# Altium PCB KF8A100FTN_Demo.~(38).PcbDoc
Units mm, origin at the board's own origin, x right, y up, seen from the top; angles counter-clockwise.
Board outline 63.75 x 27.43 mm, 2 copper layers (Top Layer, Bottom Layer); 25 components, 35 nets, 113 pads, 5 vias.
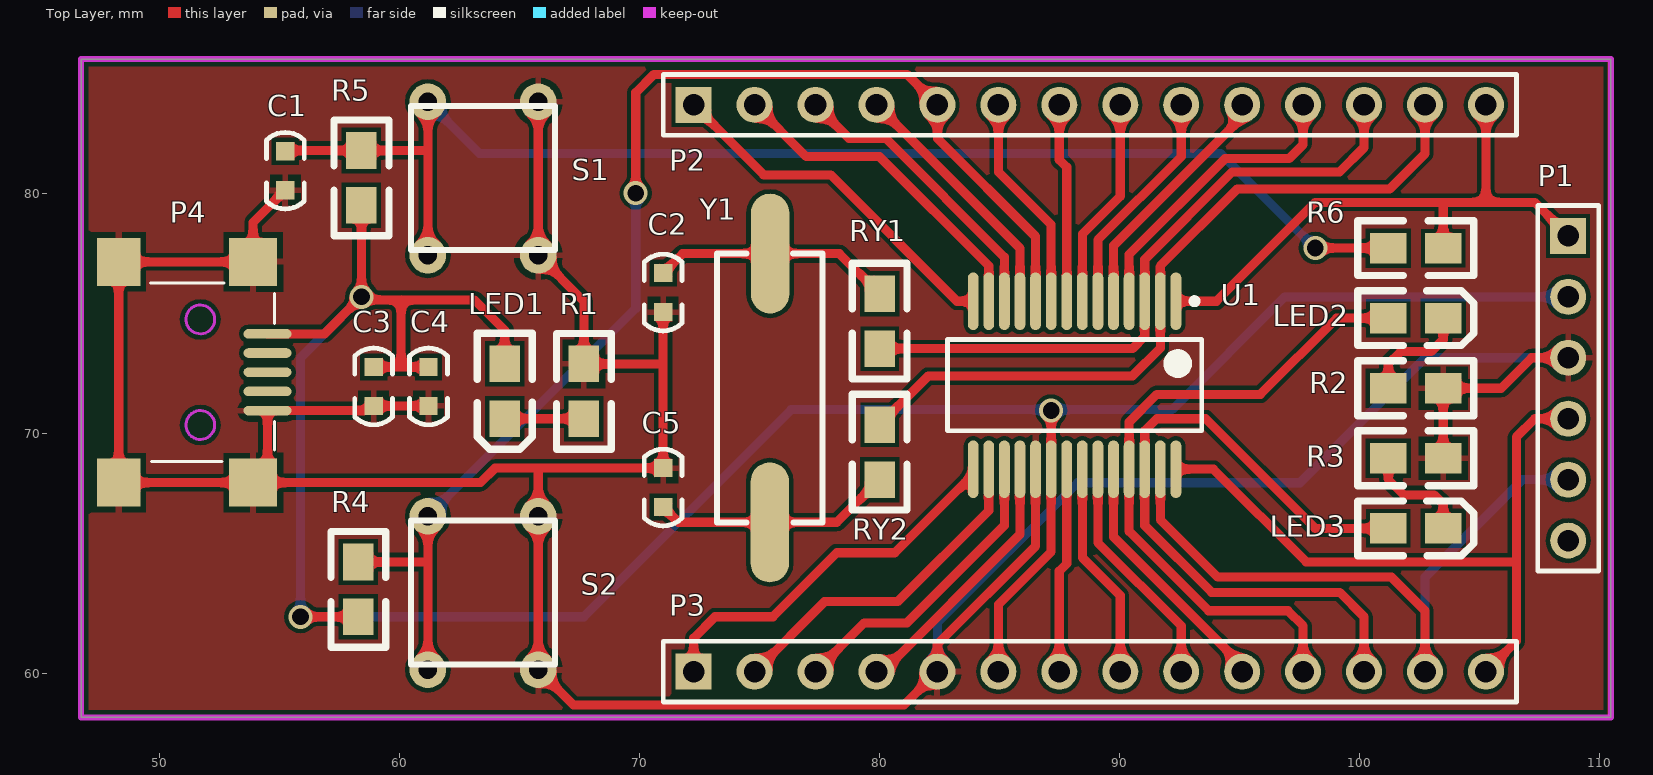
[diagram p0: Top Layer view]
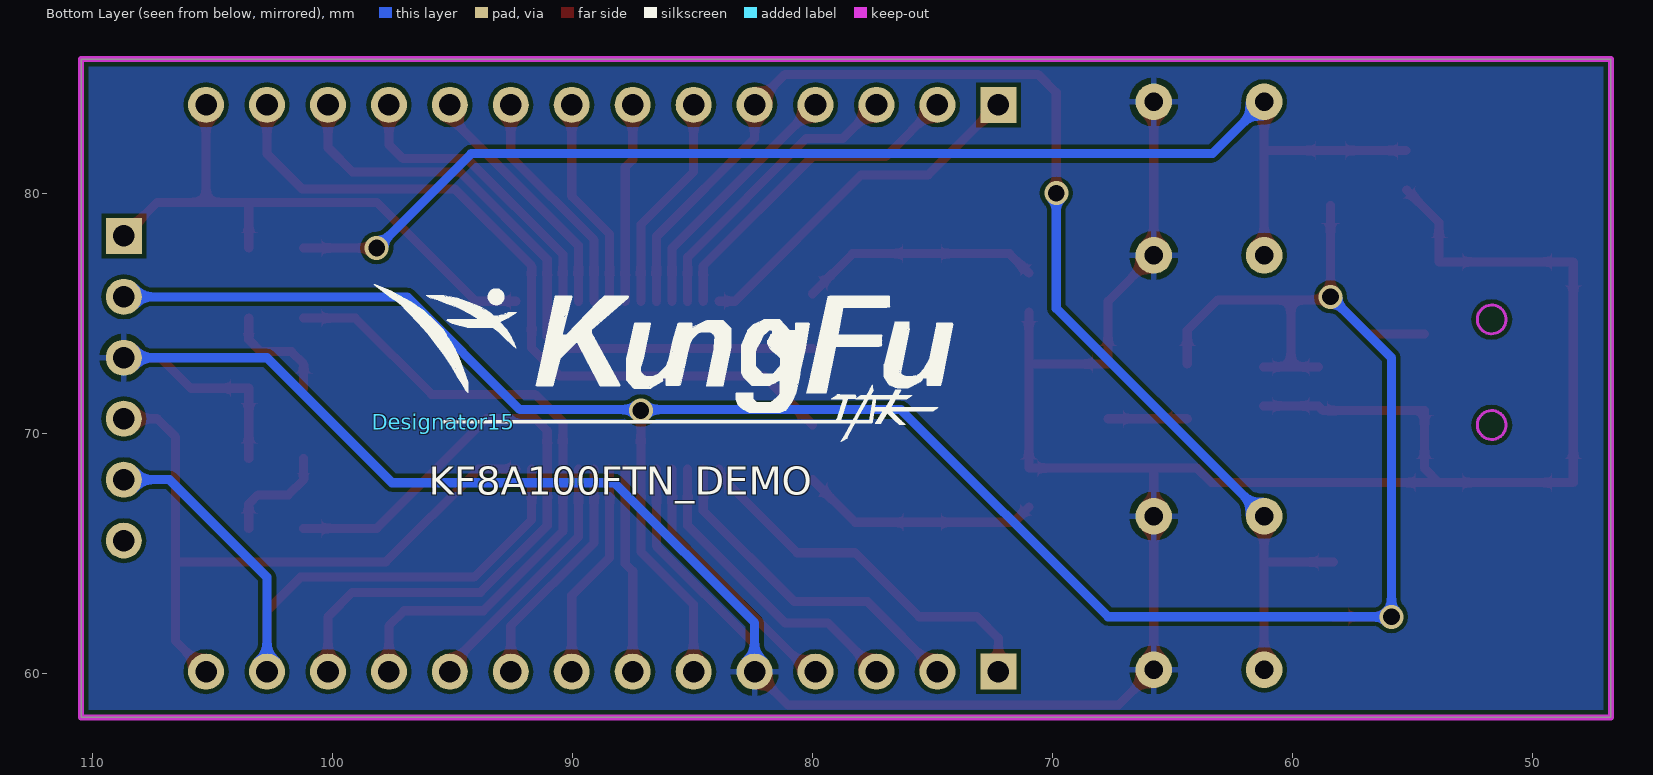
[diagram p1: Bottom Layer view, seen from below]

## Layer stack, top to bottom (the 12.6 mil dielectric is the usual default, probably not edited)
Top Solder: solder mask 0.0102, Solder Resist, Dk 3.5
Top Layer: signal copper 0.0356
Dielectric 1: dielectric 0.32, FR-4, Dk 4.8
Bottom Layer: signal copper 0.0356
Bottom Solder: solder mask 0.0102, Solder Resist, Dk 3.5

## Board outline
46.736,58.166 110.49,58.166 110.49,85.598 46.736,85.598

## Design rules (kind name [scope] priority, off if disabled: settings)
Clearance [All] p1: gap=0.178
PolygonConnect [All] p1: connectstyle=Relief reliefconductorwidth=0.254 reliefentries=4 polygonreliefangle="90 Angle" airgapwidth=0.254
RoutingVias [All] p1: holewidth=0.3 width=0.5 viastyle="Through Hole" minholewidth=0.3 minwidth=0.5 maxholewidth=0.7 maxwidth=1
SolderMaskExpansion [All] p1: expansion=0.102
UnpouredPolygon [All] p1: allowunpoured=FALSE
Width [All] p1: maxlimit=0.762 minlimit=0.254 preferedwidth=0.381
29 further rules are at their usual default settings.

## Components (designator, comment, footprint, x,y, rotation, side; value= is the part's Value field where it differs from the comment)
C1 "Comment" 0603C 55.245,80.137 r90 top
C2 "Comment" 0603C 70.993,75.057 r90 top
C3 "Comment" 0603C 58.928,72.771 r270 top
C4 "Comment" 0603C 61.214,72.771 r270 top
C5 "Comment" 0603C 70.993,66.929 r90 top
Designator15 "Comment" LOGO 95.377,70.485 r180 bottom
LED1 "Comment" D0805 64.389,72.898 r270 top
LED2 "Comment" D0805 101.216,74.803 r0 top
LED3 "Comment" D0805 101.216,66.04 r0 top
P1 "Comment" HDR1X6 108.712,78.232 r270 top
P2 "Comment" HDR1X14 72.263,83.693 r0 top
P3 "Comment" HDR1X14 72.263,60.071 r0 top
P4 "Comment" USB_MINI_B 51.562,73.406 r0 top
R1 "Comment" 0805 67.691,70.612 r90 top
R2 "Comment" 0805 101.219,71.882 r0 top
R3 "Comment" 0805 101.219,68.961 r0 top
R4 "Comment" 0805 58.293,62.357 r90 top
R5 "Comment" 0805 58.42,81.788 r270 top
R6 "Comment" 0805 101.219,77.724 r0 top
RY1 "Comment" 0805 80.01,75.819 r270 top
RY2 "Comment" 0805 80.01,70.358 r270 top
S1 "Comment" KEY6*6 65.786,83.82 r270 top
S2 "Comment" KEY6*6 65.786,66.548 r270 top
U1 "Comment" SSOP-SS28_M 88.138,72.009 r270 top
Y1 "Comment" CRYSTAL 75.438,66.294 r90 top

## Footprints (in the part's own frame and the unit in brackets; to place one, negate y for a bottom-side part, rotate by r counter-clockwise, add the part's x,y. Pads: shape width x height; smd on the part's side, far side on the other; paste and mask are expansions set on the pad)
0603C [mil]
  rect 30x30 smd: 1(0,0) 2(64,0)
  silkscreen extent -31,-31 95,31
0805 [mil]
  rect 60x50 smd: 1(-0.11,0) 2(89.89,0)
  silkscreen extent -50,-45 140,45
CRYSTAL [mm]
  oval 5x1.6 smd: 1(0,0) 2(11.2,-0.01)
  silkscreen extent 0,-2.2 11.2,2.2
D0805 [mil]
  rect 60x50 smd: 1(0,0) 2(90,0)
  silkscreen extent -50,-45 140,45
HDR1X6 [mm] "Connector; Header; 6 Position"
  rect 1.5x1.5 hole 0.9: 1(0,0)
  round 1.5 hole 0.9: 2(2.54,0) 3(5.08,0) 4(7.62,0) 5(10.16,0) 6(12.7,0)
  silkscreen extent -1.27,-1.27 13.97,1.27
HDR1X14 [mm] "Connector; Header; 14 Position"
  rect 1.5x1.5 hole 0.9: 1(0,0)
  round 1.5 hole 0.9: 2(2.54,0) 3(5.08,0) 4(7.62,0) 5(10.16,0) 6(12.7,0) 7(15.24,0) 8(17.78,0) 9(20.32,0) 10(22.86,0) 11(25.4,0) 12(27.94,0) 13(30.48,0) 14(33.02,0)
  silkscreen extent -1.27,-1.27 34.29,1.27
KEY6*6 [mil]
  round 60 hole 30: 1(0,0) 2(0,-181.1) 3(251.97,0) 4(251.97,-181.1)
  silkscreen extent 7,-209 243,28
LOGO [mm]
  silkscreen extent -2.9,-0.84 21.21,5.71
SSOP-SS28_M [mm] "SOP, 28-Leads, Body 10.2x5.2mm, Pitch 0.65mm, IPC Low Density"
  oval 2.4x0.45 smd: 1(-3.5,4.225) 2(-3.5,3.575) 3(-3.5,2.925) 4(-3.5,2.275) 5(-3.5,1.625) 6(-3.5,0.975) 7(-3.5,0.325) 8(-3.5,-0.325) 9(-3.5,-0.975) 10(-3.5,-1.625) 11(-3.5,-2.275) 12(-3.5,-2.925) 13(-3.5,-3.575) 14(-3.5,-4.225) 15(3.5,-4.225) 16(3.5,-3.575) 17(3.5,-2.925) 18(3.5,-2.275) 19(3.5,-1.625) 20(3.5,-0.975) 21(3.5,-0.325) 22(3.5,0.325) 23(3.5,0.975) 24(3.5,1.625) 25(3.5,2.275) 26(3.5,2.925) 27(3.5,3.575) 28(3.5,4.225)
  silkscreen extent -3.62,-5.3 1.9,5.3, body extent -2.7,-5.3 2.7,5.3, height 2
USB_MINI_B [mm] "USB_MINI_B"
  oval 2x0.4 smd: 1(2.941,0.744) 2(2.941,-0.056) 3(2.941,-0.856) 4(2.941,-1.656) 5(2.941,-2.456)
  rect 1.797x2 smd: 6(-3.259,-5.456) 6(-3.259,3.744)
  rect 2x2 smd: 6(2.341,-5.456) 6(2.341,3.744)
  Keep-Out Layer circle w0.127: c0.141,1.344 r0.6
  Keep-Out Layer circle w0.127: c0.141,-3.056 r0.6
  silkscreen extent -1.93,-4.58 3.24,2.85

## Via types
v1: diameter 1, hole 0.7, Top Layer to Bottom Layer, tented both sides, 5 vias

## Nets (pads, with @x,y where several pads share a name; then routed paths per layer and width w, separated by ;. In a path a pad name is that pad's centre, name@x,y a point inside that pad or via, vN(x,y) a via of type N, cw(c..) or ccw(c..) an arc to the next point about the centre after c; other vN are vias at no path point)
L1: LED1.2 R1.1 | length 3.3
  Top Layer w0.381: LED1.2 67.688,70.612 R1.1
L2: LED2.2 R2.1 | length 4.6
  Top Layer w0.381: R2.1 101.216,72.895 101.727,73.406 102.997,73.406 103.502,73.911 LED2.2
L3: LED3.2 R3.1 | length 4.6
  Top Layer w0.381: R3.1 101.216,68.075 101.854,67.437 103.124,67.437 103.502,67.059 LED3.2
P04: P2.13 RY2.1 U1.2 | length 31.5
  Top Layer w0.381: RY2.1 82.039,72.39 90.551,72.39 91.713,73.552 U1.2 91.713,76.981 94.92,80.188 101.27,80.188 102.743,81.661 P2.13
P05: P2.12 RY1.2 U1.3 | length 27.3
  Top Layer w0.381: RY1.2 90.554,73.536 91.063,74.045 U1.3 91.063,77.248 94.714,80.899 99.187,80.899 100.203,81.915 P2.12
P10: P3.4 U1.18 | length 11.1
  Top Layer w0.381: P3.4 80.137,60.071 85.863,65.797 U1.18
P11: P3.3 U1.17 | length 12.7
  Top Layer w0.381: P3.3 79.375,62.103 81.153,62.103 85.213,66.163 U1.17
P12: P3.2 U1.16 | length 14.3
  Top Layer w0.381: P3.2 77.724,62.992 80.772,62.992 84.563,66.783 U1.16
P13: P3.1 U1.15 | length 16.1
  Top Layer w0.381: P3.1 72.263,61.468 73.152,62.357 75.565,62.357 78.232,65.024 80.645,65.024 83.913,68.292 U1.15
P14: P2.1 U1.14 | length 15
  Top Layer w0.381: P2.1 75.184,80.772 77.978,80.772 83.241,75.509 U1.14
P15: P2.2 U1.13 | length 14
  Top Layer w0.381: P2.2 76.962,81.534 80.01,81.534 84.563,76.981 U1.13
P16: P2.3 U1.12 | length 12.3
  Top Layer w0.381: P2.3 78.74,82.296 80.264,82.296 85.213,77.347 U1.12
P17: P2.4 U1.11 | length 10.7
  Top Layer w0.381: P2.4 85.863,77.713 U1.11
P20: P2.11 U1.4 | length 12.7
  Top Layer w0.381: U1.4 90.413,77.459 94.412,81.458 97.079,81.458 97.663,82.042 P2.11
P21: P2.10 U1.5 | length 10.4
  Top Layer w0.381: U1.5 89.763,77.825 95.123,83.185 P2.10
P22: P2.9 U1.6 | length 9.6
  Top Layer w0.381: U1.6 89.113,78.064 92.583,81.534 P2.9
P23: P2.8 U1.7 | length 8.8
  Top Layer w0.381: U1.7 88.463,78.303 90.043,79.883 P2.8
P24: P2.7 U1.8 | length 8.3
  Top Layer w0.381: P2.7 87.503,81.407 87.813,81.097 U1.8
P25: P2.6 U1.9 | length 9.1
  Top Layer w0.381: P2.6 84.963,80.899 87.163,78.699 U1.9
P26: P2.5 R4.2 S2.2 S2.4 U1.10 | length 53.8
  Top Layer w0.381: R4.2 61.183,64.64 61.186,64.643 ; S2.4 61.186,64.643 ; S2.2 61.186,64.643 ; v1(69.85,80.01) 69.85,84.201 70.612,84.963 81.153,84.963 P2.5 82.423,82.296 86.513,78.206 U1.10
  Bottom Layer w0.381: S2.2 69.85,75.212 v1(69.85,80.01)
P30: LED3.1 P3.12 U1.26 | length 29.2
  Top Layer w0.381: P3.12 100.203,62.357 99.187,63.373 93.853,63.373 91.063,66.163 U1.26 91.063,70.108 91.567,70.612 93.599,70.612 98.171,66.04 LED3.1
P31: LED2.1 P3.11 U1.25 | length 27.9
  Top Layer w0.381: P3.11 97.663,61.976 97.028,62.611 93.726,62.611 90.413,65.924 U1.25 90.413,70.474 91.567,71.628 95.885,71.628 99.06,74.803 LED2.1
P32: P3.10 U1.24 | length 10.7
  Top Layer w0.381: U1.24 89.763,65.685 95.123,60.325 P3.10
P33: P3.9 U1.23 | length 9.9
  Top Layer w0.381: U1.23 89.113,65.446 92.583,61.976 P3.9
P34: P3.8 U1.22 | length 9.1
  Top Layer w0.381: U1.22 88.463,64.826 90.043,63.246 P3.8
P35: P3.7 U1.21 | length 8.6
  Top Layer w0.381: P3.7 87.503,64.262 87.813,64.572 U1.21
RST: P1.1 P2.14 R6.2 U1.1 | length 24.7
  Top Layer w0.381: U1.1 94.051,75.509 98.171,79.629 103.378,79.629 ; R6.2 103.502,79.505 103.378,79.629 ; P2.14 105.283,79.629 ; P1.1 107.315,79.629 105.283,79.629 ; 103.378,79.629 105.283,79.629
S2: C1.2 R5.1 R6.1 S1.2 S1.4 | length 54.7
  Top Layer w0.381: C1.2@55.273,81.791 R5.1 61.062,81.791 ; S1.4 S1.2 ; v1(98.171,77.724) R6.1
  Bottom Layer w0.381: S1.2 63.345,81.661 94.234,81.661 v1(98.171,77.724)
S2-1: 
SPCLK: P1.5 P3.13 U1.27 | length 28.8
  Top Layer w0.381: U1.27 91.713,66.402 94.107,64.008 101.346,64.008 102.743,62.611 P3.13
  Bottom Layer w0.381: P3.13 102.743,64.008 106.807,68.072 P1.5
SPDAT: P1.4 P3.14 U1.28 | length 28.4
  Top Layer w0.381: U1.28 93.924,68.509 97.79,64.643 106.426,64.643 ; P3.14 106.553,61.341 106.553,69.85 107.315,70.612 P1.4
VDD: C3.1 C4.1 LED1.1 P1.2 P3.6 P4.1 R4.1 R5.2 U1.20 | length 108.5
  Top Layer w0.381: P4.1 56.878,74.15 v1@58.293,75.565 ; v1(55.88,62.357) R4.1@58.29,62.357 ; R5.2 v1(58.42,75.692) v1@58.293,75.565 ; C3.1 60.071,72.771 ; C4.1 60.071,72.771 ; LED1.1 64.389,74.295 63.119,75.565 60.071,75.565 ; P3.6 84.963,62.865 87.163,65.065 U1.20 v1(87.163,70.952) ; v1@58.293,75.565 60.071,75.565 ; 60.071,72.771 60.071,75.565
  Bottom Layer w0.381: v1(58.42,75.692) 55.88,73.152 v1(55.88,62.357) 67.691,62.357 76.327,70.993 v1@87.122,70.993 ; v1(87.163,70.952) v1@87.122,70.993 ; P1.2 96.901,75.692 92.202,70.993 v1@87.122,70.993
VSS: C1.1 C2.1 C3.2 C4.2 C5.2 P1.3 P3.5 P4.5 P4.6 R1.2 R2.2 R3.2 S1.1 S1.3 S2.1 S2.3 U1.19 | length 150.7
  Top Layer w0.381: C1.1 53.903,78.795 53.903,77.15 48.303,77.15 48.303,67.95 P4.6@53.903,67.95 ; C4.2 C3.2 58.732,70.95 P4.5 54.503,68.55 P4.6@53.903,67.95 ; 65.786,68.453 S2.1 S2.3 67.26,58.674 81.026,58.674 P3.5 82.423,61.214 86.513,65.304 U1.19 ; S1.1 S1.3 67.691,75.515 R1.2 70.99,72.895 70.993,72.898 ; C2.1 70.993,72.898 ; R3.2 R2.2 105.918,71.882 107.188,73.152 P1.3 ; P4.6@53.903,67.95 63.378,67.95 63.983,68.555 C5.2 70.993,72.898
  Bottom Layer w0.381: P3.5 82.423,62.103 88.265,67.945 97.536,67.945 102.743,73.152 P1.3
Y1: C5.1 RY2.2 Y1.1 | length 10
  Top Layer w0.381: C5.1 71.628,66.294 Y1.1 78.229,66.294 RY2.2
Y2: C2.2 RY1.1 Y1.2 | length 10
  Top Layer w0.381: C2.2 71.804,77.494 Y1.2 78.338,77.494 RY1.1
pads on no net: P1.6 P4.2 P4.3 P4.4

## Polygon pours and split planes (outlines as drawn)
no net on Top Layer "Top Layer-No Net" (solid, remove dead copper, shelved, pour order 2): 46.736,85.598 110.363,85.598 110.363,58.293 110.49,58.166 46.736,58.166
VSS on Top Layer "Top Layer-No Net" (solid, remove dead copper, pour order 2): 46.736,85.598 110.363,85.598 110.363,58.293 110.49,58.166 46.736,58.166
VSS on Bottom Layer "Top Layer-No Net" (solid, remove dead copper, pour order 5): 46.736,85.598 110.49,85.598 110.49,58.166 46.736,58.166

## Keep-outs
Keep-Out Layer:
  the board outline again, w0.254

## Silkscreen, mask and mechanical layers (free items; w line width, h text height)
Bottom Overlay:
  text "KF8A100FTN_DEMO" at 96.012,67.056 h2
